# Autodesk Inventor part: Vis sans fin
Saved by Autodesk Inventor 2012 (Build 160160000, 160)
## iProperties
Created: 2011-07
Part Number: Vis sans fin
Material: Acier doux
Document SubType Name: Modeling
Designer: Laur
Density: 7.86 g/cm^3
CustomPartVersion: 1
Author: Laur
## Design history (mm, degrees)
node "Solide1"
node "Corps solides"
node "Corps surfaciques"
extrude "Corps de base" new body stored distance "d6" = 8 (= da_b); taper "d7" = 0 deg
chamfer "Chamfer1" distance "d8" = 0.40037 (= fd_cham1); stored, may be unused: second distance "d9" = 1.1 (= 0.5 x fd_cham2), angle "d47" = 45 deg
chamfer "Chamfer2" distance "d10" = 0.40037 (= fd_cham1); stored, may be unused: second distance "d11" = 1.1 (= 0.5 x fd_cham2), angle "d48" = 45 deg
sketch "Esquisse de la dent"
  geometry: L1 (0, 21.74)-(0, 10.96) reference; L2 (-6.115, 2.921)-(-5.705, 1.792); L3 (-5.352, 1.792)-(-4.941, 2.921); L4 (-50.535, 0)-(-37.455, 0) reference; L5 (-6.115, 2.921)-(-5.528, 2.921); L6 (-5.528, 2.921)-(-4.941, 2.921); L7 (-5.705, 1.792)-(-5.528, 1.792); L8 (-5.528, 1.792)-(-5.352, 1.792); L9 (-5.528, 2.392)-(-5.133, 2.392); L10 (-5.528, 2.921)-(-5.528, 1.792)
  constraints: 16 end point, 3 equal length, 3 parallel, 2 collinear, 2 point on line
  dimensions: "d24" = 110 deg angle of L7 L2 (computed from da_alfat); "d25" = 5.52807 distance from line of L1 L5.end (= fd_dist); "d26" = 0.39486 distance of L9.start L9.end (= 0.25 x da_px); "d27" = 1.79169 distance between parallel lines of L4 L7 (= 0.5 x da_df); "d28" = 2.39169 distance between parallel lines of L4 L9 (= 0.5 x da_d); "d29" = 2.92061 distance between parallel lines of L4 L5 (= 0.505 x da_da)
feature "Dent" pitch "d30" = 1.57945 (computed from da_px, da_z); turns "d32" = 8 (= fd_n); dims "d31" = 10, "d33" = 0, angle "d34" = 90 deg, angle "d35" = 90 deg, "d36" = 0, "d37" = 0, "d70" = 10, "da_rightdir" = 10 [user parameter]
pattern_circular "Motif de la dent" dims angle "d46" = 360 deg
feature "Dent gauche" pitch "d62" = 1.57945 (computed from da_px, da_z); turns "d64" = 8 (= fd_n); dims "d63" = 10, "d65" = 0, angle "d66" = 90 deg, angle "d67" = 90 deg, "d68" = 0, "d69" = 0, "d76" = 10, "da_rightdir" = 10 [user parameter]
pattern_circular "Motif de dent gauche" dims angle "d73" = 360 deg
node "Esquisse du corps de base" dims "d5" = 5.78339 (= da_da)
sketch "Sketch5"
  geometry: C1 r 2.892 at (0, 0) reference; C2 r 2.392 at (0, 0)
  constraints: 1 centre point, 1 coincident
  dimensions: "d59" = 4.78339 diameter of C2 (= da_d)
body "Srf1"
extrude_surface "ExtrusionSrf1" dims "d60" = 10, "d61" = 0
other parameters: "da_aw" = 9.93301 [user parameter; used in 2 equation terms], "da_b" = 8 [user parameter; used in 3 equation terms], "da_df" = 3.58339 [user parameter; used in 2 equation terms], "da_da" = 5.78339 [user parameter; used in 3 equation terms], "fd_cham2" = 2.2 (= da_da - da_df) [user parameter; used in 3 equation terms], "fd_cham1" = 0.40037 (= 0.181985 x fd_cham2) [user parameter; used in 2 equation terms], "da_d" = 4.78339 [user parameter; used in 2 equation terms], "da_px" = 1.57945 [user parameter; used in 5 equation terms], "fd_dist" = 5.52807 (computed from da_b, da_px) [user parameter; used in 1 equation term], "fd_n" = 8 (computed from da_b, da_px) [user parameter; used in 2 equation terms], "da_alfat" = 20 deg [user parameter; used in 1 equation term], "d12" = 110 deg (derived), "d14" = 3.1425 (derived), "d49" = 9.93301 (= da_aw), "d50" = 0, "d54" = 0, "d56" = 0, "d77" = 0, "d79" = 9.93301 (= da_aw), "d80" = 0
